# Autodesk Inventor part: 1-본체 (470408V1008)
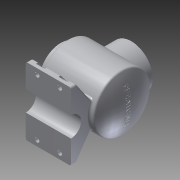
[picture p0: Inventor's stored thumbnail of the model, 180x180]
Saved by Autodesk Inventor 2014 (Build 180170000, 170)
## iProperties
Created: 2017-04
Part Number: 1-본체 (470408V1008)
Material: Aluminum 6061
Document SubType Name: Modeling
Designer: user
Density: 2.71 g/cm^3
Appearance: Aluminum - Flat
Author: user
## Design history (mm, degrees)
sketch "Sketch1"
  geometry: L1 (-60, 0)-(60, 0); L2 (-60, 38)-(-60, 27); L3 (-60, 38)-(-48, 38); L4 (-48, 38)-(-48, 50); L5 (-48, 50)-(48.336, 50); L6 (-60, 27)-(-38, 27); L7 (-38, 27)-(-38, 40); L8 (-38, 40)-(42.47, 40); A1 r 113 centre (-53, 0) between (60, 0) and (48.336, 50); A2 r 110 centre (-60, 0) between (50, 0) and (42.47, 40); 2 further points
  constraints: 16 end point, 5 perpendicular, 4 point on circle, 2 centre point, 2 coincident, 1 horizontal, 1 midpoint, 1 parallel, 1 point on line
  dimensions: "d3" = 11 distance of L2.start L2.end; "d4" = 12 distance of L3.end L2.start; "d5" = 76 diameter of L2.start L1; "d9" = 100 diameter of L4.end L1; "d10" = 22 distance of L6.end L2.end; "d13" = 54 diameter of L2.end L1
revolve "Revolution1" sketch "Sketch1" stored, may be unused: angle "d14" = 90 deg
workplane "Work Plane1"
sketch "Sketch2"
  geometry: C1 r 38 at (0, 0); 1 further point
  constraints: 1 centre point, 1 coincident
  dimensions: "d16" = 76 diameter of C1
extrude "Extrusion1" join sketch "Sketch2" stored distance "d17" = 10; taper "d18" = 0 deg
sketch "Sketch3"
  geometry: C1 r 38 at (0, 0) reference; C2 r 27 at (0, 0)
  constraints: 1 centre point, 1 coincident
  dimensions: "d19" = 54 diameter of C2
extrude "Extrusion2" cut sketch "Sketch3" distance "d20" = 40; taper "d21" = 0 deg
sketch "Sketch4"
  geometry: 4 further points
sketch "Sketch5"
  geometry: 4 further points
hole "Hole1" sketch "Sketch4" diameter "d24" = 3.242; stored, may be unused: countersink angle "d28" = 90 deg, drill point angle "d30" = 118 deg; dims "d25" = 8, "d26" = 4, "d27" = 2, "d29" = 10
hole "Hole2" sketch "Sketch5" diameter "d31" = 3.242; stored, may be unused: countersink angle "d35" = 90 deg, drill point angle "d37" = 118 deg; dims "d32" = 8, "d33" = 4, "d34" = 2, "d36" = 10
workplane "Work Plane3"
sketch "Sketch7"
  geometry: L1 (-60, -82)-(-60, -72); L2 (-60, -82)-(60, -82); L3 (60, -82)-(60, -72); L4 (-60, -72)-(-21.584, -45.101); L5 (60, -72)-(21.584, -45.101); A1 r 50 centre (0, 0) between (-21.584, -45.101) and (21.584, -45.101); 2 further points
  constraints: 10 end point, 2 perpendicular, 2 point on circle, 1 centre point, 1 coincident, 1 midpoint, 1 vertical alignment
  dimensions: "d44" = 10 distance of L1.start L1.end; "d45" = 120 distance of L1.start L2.end; "d46" = 10 distance of L2.end L3.end; "d58" = 55 deg angle of L1 L4; "d64" = 55 deg angle of L3 L5; "d65" = 50 radius of A1
extrude "Extrusion3" join sketch "Sketch7" distance "d66" = 80; taper "d67" = 0 deg
sketch "Sketch8"
  geometry: L1 (60, -72)-(60, -82) reference; L2 (-18, -82)-(18, -82); A1 r 18 centre (0, -82) between (18, -82) and (-18, -82)
  constraints: 2 end point, 2 point on circle, 1 centre point, 1 perpendicular
  dimensions: "d70" = 18 radius of A1
extrude "Extrusion4" cut sketch "Sketch8" stored distance "d71" = 80; taper "d72" = 0 deg
workplane "Work Plane4"
sketch "Sketch13"
  geometry: L1 (0, 0)-(0, -42) reference; L2 (80, 0)-(80, -42) reference; L3 (12, 0)-(28, 0); L4 (12, -10)-(12, 0); L5 (28, -10)-(28, 0); A1 r 8 centre (20, -10) between (12, -10) and (28, -10); 1 further point
  constraints: 6 end point, 2 point on circle, 2 tangent, 1 centre point
  dimensions: "d93" = 16 distance of L3.start L3.end; "d96" = 20 horizontal distance of A1.centre L1.start; "d97" = 10 vertical distance of A1.centre L3.end
extrude "Extrusion8" cut sketch "Sketch13" distance "d98" = 40; taper "d99" = 0 deg
sketch "Sketch14"
  geometry: C1 r 4 at (20, 10); A1 r 8 centre (20, 10) between (28, 10) and (12, 10) reference; 1 further point
  constraints: 1 centre point, 1 coincident
  dimensions: "d100" = 8 diameter of C1
extrude "Extrusion9" cut sketch "Sketch14" stored distance "d101" = 10; taper "d102" = 0 deg
mirror "Mirror1"
mirror "Mirror2"
workplane "Work Plane5"
sketch "Sketch15"
  geometry: L1 (-82, 60)-(-82, 18) reference; A1 r 18 centre (-82, 0) between (-82, -18) and (-82, 18) reference; 2 further points
  constraints: 1 other
  dimensions: "d104" = 82 distance of point (0, 0) A1.centre; "d105" = 60 vertical distance of point (0, 0) L1.start
emboss "Emboss1" sketch "Sketch15" dims "d3" = 11, "d106" = 0.5, "d107" = 0
fillet "Fillet1" dims "d108" = 3
fillet "Fillet2" dims "d109" = 3
chamfer "Chamfer1" distance "d110" = 1; stored, may be unused: second distance "d111" = 2, angle "d112" = 45 deg
chamfer "Chamfer2" distance "d113" = 1; stored, may be unused: second distance "d114" = 2, angle "d115" = 45 deg
fillet "Fillet3" dims "d116" = 3
body "Solid1"
other parameters: "d15" = 65, "d41" = -8, "d83" = -6
